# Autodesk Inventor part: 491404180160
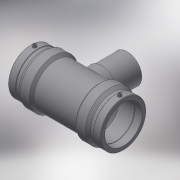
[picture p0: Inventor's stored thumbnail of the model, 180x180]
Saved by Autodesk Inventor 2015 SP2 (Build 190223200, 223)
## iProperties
Created: 2017-06
Part Number: 491404180160
Material: Generic
Description: PLASSON REDUCING TEE 180x160x180
Document SubType Name: Modeling
Designer: KIM
Mass: 8265.31 g
Surface Area: 7031.62 cm^2
Volume: 8265.31 cm^3
Density: 1 g/cm^3
Appearance: Default
Author: KIM
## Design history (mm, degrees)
derived "491404.ipt"
feature "Solid1::491404.ipt"
tag "TaggingFeature1"
body "Solid1"
other parameters: "d0" = 422, "d2" = 245, "d3" = 106, "d4" = 84.4, "d5" = 220.5, "d6" = 171, "d8" = 168 deg, "d10" = 42.4, "d11" = 14.13333, "d13" = 422, "d14" = 17.6296, "d17" = 162, "d19" = 3.52592, "d20" = 168 deg, "d22" = 227.85, "d23" = 245, "d25" = 135 deg, "d26" = 295.4, "d29" = 116, "d30" = 15, "d31" = 168.8, "d34" = 5 deg, "d35" = 15, "d39" = 5 deg, "d41" = 4, "d42" = 14, "d43" = 0, "d45" = 4, "d46" = 6, "d47" = 0, "d51" = 0, "d52" = 128, "d54" = 0, "d55" = 220.5, "d56" = 245, "d57" = 147.7, "d58" = 135 deg, "d59" = 106, "d60" = 106, "d61" = 135 deg, "d72" = 192.01, "d73" = 96.005, "d75" = 168, "d77" = 0, "d78" = 128, "d80" = 0, "d82" = 127.5, "d83" = 0, "d84" = 3, "d85" = 0, "d86" = 35.33333, "d87" = 223.293, "d88" = 14.13333, "d89" = 3, "d90" = 0, "L_" = 422, "L_1" = 106, "D_" = 245, "A_" = 116, "d_2" = 12
